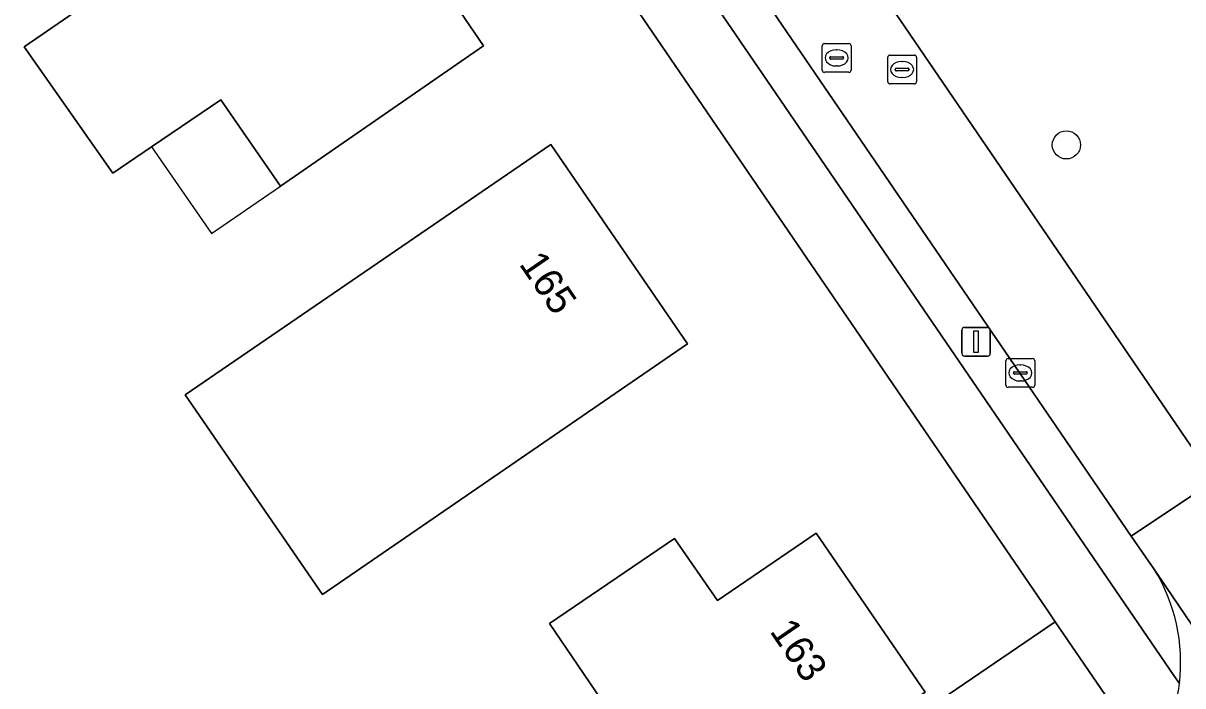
# Model space of a CAD drawing. Extents: x 155275 to 156265, y 382654 to 383635.
# Drawn here: x 155582.54 to 155622.86, y 383266.52 to 383289.56 of the extents above; entities that cross this region are included whole.
import ezdxf

# ---------------------------------------------------------------- set-up
doc = ezdxf.new("R2010")
doc.units = 0
for name, color, linetype in [('IMGEO_Boom', 7, 'Continuous'), ('IMGEO_Erf', 7, 'Continuous'), ('IMGEO_Groenvoorziening', 7, 'Continuous'), ('IMGEO_Haag', 7, 'Continuous'), ('IMGEO_Kolk', 7, 'Continuous'), ('IMGEO_Lichtmast', 7, 'Continuous'), ('IMGEO_Pand', 7, 'Continuous'), ('IMGEO_Pand_nummerreeks', 7, 'Continuous'), ('IMGEO_Pand_overbouw', 7, 'Continuous'), ('IMGEO_Rijbaan_lokaal_gesloten', 7, 'Continuous'), ('IMGEO_Rijbaan_lokaal_open', 7, 'Continuous'), ('IMGEO_Rioolput', 7, 'Continuous'), ('IMGEO_Voetpad_open', 7, 'Continuous')]:
    doc.layers.add(name, color=color, linetype=linetype)

msp = doc.modelspace()

# ---------------------------------------------------------------- linework, layer by layer
at = {"layer": 'IMGEO_Boom'}
msp.add_circle((155618.813, 383285.326), 0.489, dxfattribs=at)
at = {"layer": 'IMGEO_Erf'}
for points in [[(155554.524, 383362.222), (155521.756, 383339.814), (155585.616, 383246.401), (155618.427, 383268.752), (155618.124, 383269.195)], [(155591.706, 383295.013), (155592.486, 383293.88), (155594.248, 383295.079), (155598.542, 383288.767), (155591.485, 383283.889), (155589.408, 383286.892), (155587.003, 383285.257), (155585.659, 383284.344), (155582.572, 383288.731)], [(155600.891, 383285.34), (155605.638, 383278.407), (155592.942, 383269.696), (155588.177, 383276.635)], [(155603.23, 383265.176), (155600.839, 383268.693), (155605.185, 383271.648), (155606.676, 383269.488), (155610.115, 383271.826), (155613.901, 383266.307), (155610.43, 383263.967), (155610.684, 383263.596), (155609.065, 383262.49), (155608.775, 383262.901), (155607.675, 383262.154), (155607.956, 383261.74), (155606.324, 383260.632), (155606.21, 383260.801), (155599.65, 383256.349), (155599.774, 383256.167), (155599.512, 383255.988), (155596.412, 383260.518)]]:
    msp.add_lwpolyline(points, close=True, dxfattribs=at)
at = {"layer": 'IMGEO_Groenvoorziening'}
for points in [[(155561.654, 383364.944), (155563.253, 383362.574), (155623.958, 383273.666), (155629.922, 383264.93), (155630.7, 383265.467)], [(155560.376, 383360.557), (155559.574, 383361.726), (155559.546, 383361.767), (155558.233, 383360.928), (155622.545, 383266.887), (155622.743, 383266.603)], [(155621.859, 383270.595), (155621.067, 383271.724), (155560.376, 383360.557)]]:
    msp.add_lwpolyline(points, dxfattribs=at)
msp.add_arc((155616.588, 383267.334), 6.198, 353.2276, 31.7449, dxfattribs=at)
at = {"layer": 'IMGEO_Haag'}
for points in [[(155560.376, 383360.557), (155559.574, 383361.726), (155559.546, 383361.767), (155558.233, 383360.928), (155622.545, 383266.887), (155622.743, 383266.603)], [(155621.859, 383270.595), (155621.067, 383271.724), (155560.376, 383360.557)]]:
    msp.add_lwpolyline(points, dxfattribs=at)
msp.add_arc((155616.588, 383267.334), 6.198, 353.2276, 31.7449, dxfattribs=at)
at = {"layer": 'IMGEO_Kolk'}
for p, q in [((155616.711, 383276.974), (155616.711, 383277.826)), ((155616.786, 383277.9), (155617.638, 383277.9)), ((155617.712, 383277.826), (155617.712, 383276.974)), ((155616.97, 383277.394), (155616.97, 383277.406)), ((155617.013, 383277.443), (155617.411, 383277.443)), ((155617.199, 383277.68), (155617.224, 383277.68)), ((155617.454, 383277.406), (155617.454, 383277.394)), ((155617.408, 383277.357), (155617.01, 383277.357)), ((155617.222, 383277.12), (155617.197, 383277.12)), ((155617.638, 383276.9), (155616.786, 383276.9))]:
    msp.add_line(p, q, dxfattribs=at)
for points in [[(155616.711, 383276.974), (155616.711, 383277.826)], [(155616.786, 383277.9), (155617.638, 383277.9)], [(155617.712, 383277.826), (155617.712, 383276.974)], [(155617.638, 383276.9), (155616.786, 383276.9)]]:
    msp.add_lwpolyline(points, dxfattribs=at)
for centre, radius, start, end in [((155616.788, 383277.824), 0.0765, 91.552, 178.448), ((155616.788, 383277.824), 0.0765, 91.552, 178.448), ((155617.636, 383277.824), 0.0765, 1.552, 88.448), ((155617.636, 383277.824), 0.0765, 1.552, 88.448), ((155617.01, 383277.403), 0.0403, 85.8775, 175.7526), ((155617.415, 383277.405), 0.0386, 1.7309, 96.639), ((155617.007, 383277.393), 0.0366, 178.938, 274.7102), ((155617.411, 383277.4), 0.043, 264.8664, 352.4533), ((155616.788, 383276.976), 0.0765, 181.552, 268.448), ((155616.788, 383276.976), 0.0765, 181.552, 268.448), ((155617.636, 383276.976), 0.0765, 271.552, 358.448), ((155617.636, 383276.976), 0.0765, 271.552, 358.448)]:
    msp.add_arc(centre, radius, start, end, dxfattribs=at)
for centre, major_axis, ratio, start_param, end_param in [((155617.198, 383277.4), (-0.387, 0.002), 0.722429, 4.712389, 7.853982), ((155617.223, 383277.4), (-0.39, 0.002), 0.717154, 1.570796, 4.712389)]:
    msp.add_ellipse(centre, major_axis=major_axis, ratio=ratio, start_param=start_param, end_param=end_param, dxfattribs=at)
at = {"layer": 'IMGEO_Lichtmast'}
for p, q in [((155615.176, 383278.083), (155615.176, 383278.883)), ((155615.176, 383278.883), (155615.176, 383278.083)), ((155615.276, 383278.983), (155616.066, 383278.983)), ((155616.066, 383278.983), (155615.276, 383278.983)), ((155616.166, 383278.883), (155616.166, 383278.083)), ((155616.166, 383278.083), (155616.166, 383278.883)), ((155616.066, 383277.983), (155615.276, 383277.983)), ((155615.276, 383277.983), (155616.066, 383277.983))]:
    msp.add_line(p, q, dxfattribs=at)
msp.add_lwpolyline([(155615.596, 383278.858), (155615.746, 383278.858), (155615.746, 383278.108), (155615.596, 383278.108), (155615.596, 383278.858)], dxfattribs=at)
for centre, start, end in [((155615.276, 383278.883), 90, 180), ((155615.276, 383278.883), 90, 180), ((155616.066, 383278.883), 0, 90), ((155616.066, 383278.883), 360, 90), ((155615.276, 383278.083), 180, 270), ((155615.276, 383278.083), 180, 270), ((155616.066, 383278.083), 270, 0), ((155616.066, 383278.083), 270, 0)]:
    msp.add_arc(centre, 0.1, start, end, dxfattribs=at)
at = {"layer": 'IMGEO_Pand'}
for points in [[(155585.659, 383284.344), (155587.003, 383285.257), (155589.408, 383286.892), (155591.485, 383283.889), (155598.542, 383288.767), (155594.248, 383295.079), (155592.486, 383293.88), (155591.706, 383295.013), (155582.572, 383288.731)], [(155592.942, 383269.696), (155605.638, 383278.407), (155600.891, 383285.34), (155588.177, 383276.635)], [(155599.512, 383255.988), (155599.774, 383256.167), (155599.65, 383256.349), (155606.21, 383260.801), (155606.324, 383260.632), (155607.956, 383261.74), (155607.675, 383262.154), (155608.775, 383262.901), (155609.065, 383262.49), (155610.684, 383263.596), (155610.43, 383263.967), (155613.901, 383266.307), (155610.115, 383271.826), (155606.676, 383269.488), (155605.185, 383271.648), (155600.839, 383268.693), (155603.23, 383265.176), (155596.412, 383260.518)]]:
    msp.add_lwpolyline(points, close=True, dxfattribs=at)
at = {"layer": 'IMGEO_Pand_overbouw'}
msp.add_lwpolyline([(155591.485, 383283.889), (155589.408, 383286.892), (155587.003, 383285.257), (155589.083, 383282.242)], close=True, dxfattribs=at)
at = {"layer": 'IMGEO_Rijbaan_lokaal_gesloten'}
msp.add_lwpolyline([(155563.253, 383362.574), (155560.376, 383360.557), (155621.067, 383271.724), (155623.958, 383273.666)], close=True, dxfattribs=at)
msp.add_lwpolyline([(155623.958, 383273.666), (155621.067, 383271.724), (155621.859, 383270.595), (155630.636, 383257.644)], dxfattribs=at)
at = {"layer": 'IMGEO_Rijbaan_lokaal_open'}
msp.add_lwpolyline([(155630.636, 383257.644), (155621.859, 383270.595)], dxfattribs=at)
for centre, radius, start, end in [((155616.588, 383267.334), 6.198, 353.2276, 31.7449), ((155616.542, 383267.348), 6.246, 326.4491, 353.1502)]:
    msp.add_arc(centre, radius, start, end, dxfattribs=at)
at = {"layer": 'IMGEO_Rioolput'}
for p, q in [((155610.323, 383287.924), (155610.323, 383288.776)), ((155610.398, 383288.85), (155611.25, 383288.85)), ((155611.324, 383288.776), (155611.324, 383287.924)), ((155610.582, 383288.344), (155610.582, 383288.356)), ((155611.02, 383288.307), (155610.622, 383288.307)), ((155610.625, 383288.393), (155611.023, 383288.393)), ((155610.811, 383288.63), (155610.836, 383288.63)), ((155611.066, 383288.356), (155611.066, 383288.344)), ((155612.601, 383287.523), (155612.601, 383288.375)), ((155612.676, 383288.449), (155613.528, 383288.449)), ((155613.602, 383288.375), (155613.602, 383287.523)), ((155610.834, 383288.07), (155610.809, 383288.07)), ((155612.86, 383287.943), (155612.86, 383287.955)), ((155613.298, 383287.906), (155612.9, 383287.906)), ((155612.903, 383287.992), (155613.301, 383287.992)), ((155613.089, 383288.229), (155613.114, 383288.229)), ((155613.344, 383287.955), (155613.344, 383287.943)), ((155611.25, 383287.85), (155610.398, 383287.85)), ((155613.112, 383287.669), (155613.087, 383287.669)), ((155613.528, 383287.449), (155612.676, 383287.449))]:
    msp.add_line(p, q, dxfattribs=at)
for points in [[(155610.323, 383287.924), (155610.323, 383288.776)], [(155610.398, 383288.85), (155611.25, 383288.85)], [(155611.324, 383288.776), (155611.324, 383287.924)], [(155612.601, 383287.523), (155612.601, 383288.375)], [(155612.676, 383288.449), (155613.528, 383288.449)], [(155613.602, 383288.375), (155613.602, 383287.523)], [(155611.25, 383287.85), (155610.398, 383287.85)], [(155613.528, 383287.449), (155612.676, 383287.449)]]:
    msp.add_lwpolyline(points, dxfattribs=at)
for centre, radius, start, end in [((155610.4, 383288.774), 0.0765, 91.552, 178.448), ((155610.4, 383288.774), 0.0765, 91.552, 178.448), ((155611.248, 383288.774), 0.0765, 1.552, 88.448), ((155611.248, 383288.774), 0.0765, 1.552, 88.448), ((155610.622, 383288.353), 0.0403, 85.8775, 175.7526), ((155610.619, 383288.343), 0.0366, 178.938, 274.7102), ((155611.023, 383288.35), 0.043, 264.8664, 352.4533), ((155611.027, 383288.355), 0.0386, 1.7309, 96.639), ((155612.678, 383288.373), 0.0765, 91.552, 178.448), ((155612.678, 383288.373), 0.0765, 91.552, 178.448), ((155613.526, 383288.373), 0.0765, 1.552, 88.448), ((155613.526, 383288.373), 0.0765, 1.552, 88.448), ((155610.4, 383287.926), 0.0765, 181.552, 268.448), ((155610.4, 383287.926), 0.0765, 181.552, 268.448), ((155611.248, 383287.926), 0.0765, 271.552, 358.448), ((155611.248, 383287.926), 0.0765, 271.552, 358.448), ((155612.9, 383287.952), 0.0403, 85.8775, 175.7526), ((155612.897, 383287.942), 0.0366, 178.938, 274.7102), ((155613.301, 383287.949), 0.043, 264.8664, 352.4533), ((155613.305, 383287.954), 0.0386, 1.7309, 96.639), ((155612.678, 383287.525), 0.0765, 181.552, 268.448), ((155612.678, 383287.525), 0.0765, 181.552, 268.448), ((155613.526, 383287.525), 0.0765, 271.552, 358.448), ((155613.526, 383287.525), 0.0765, 271.552, 358.448)]:
    msp.add_arc(centre, radius, start, end, dxfattribs=at)
for centre, major_axis, ratio, start_param, end_param in [((155610.81, 383288.35), (-0.387, 0.002), 0.722429, 4.712389, 7.853982), ((155610.835, 383288.35), (-0.39, 0.002), 0.717154, 1.570796, 4.712389), ((155613.088, 383287.949), (-0.387, 0.002), 0.722429, 4.712389, 7.853982), ((155613.113, 383287.949), (-0.39, 0.002), 0.717154, 1.570796, 4.712389)]:
    msp.add_ellipse(centre, major_axis=major_axis, ratio=ratio, start_param=start_param, end_param=end_param, dxfattribs=at)
at = {"layer": 'IMGEO_Voetpad_open'}
for points in [[(155558.233, 383360.928), (155559.546, 383361.767), (155559.538, 383361.779), (155557.903, 383364.172), (155554.524, 383362.222), (155618.124, 383269.195), (155618.427, 383268.752), (155621.747, 383263.896)], [(155622.743, 383266.603), (155622.545, 383266.887), (155558.233, 383360.928)], [(155621.747, 383263.896), (155618.427, 383268.752), (155585.616, 383246.401), (155584.391, 383245.552), (155585.69, 383243.652)]]:
    msp.add_lwpolyline(points, dxfattribs=at)
msp.add_arc((155616.542, 383267.348), 6.246, 326.4491, 353.1502, dxfattribs=at)

# ---------------------------------------------------------------- texts
at = {"layer": 'IMGEO_Pand_nummerreeks'}
for s, rotation, p in [('165', 304.4091, (155599.759, 383281.186)), ('163', 304.449, (155608.474, 383268.419))]:
    msp.add_text(s, height=1, rotation=rotation, dxfattribs=at).set_placement(p)

doc.saveas('drawing.dxf')
